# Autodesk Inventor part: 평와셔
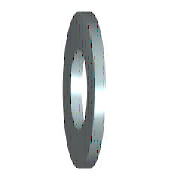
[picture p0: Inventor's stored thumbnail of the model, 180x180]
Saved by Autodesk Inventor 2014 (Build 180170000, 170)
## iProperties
IsCustomPart: 1
Created: 2012-02
Part Number: 평와셔
Material: 강철
Description: 평면 와셔 - 초대형 시리즈 - 제품 등급 C
Document SubType Name: Modeling
Standard: ISO 7094
Designer: mduedu
Standard Revision: Second edition 2000-06-01
Standards Organization: ISO
Language: ko-KR
Size Designation: ST 5 - 100 HV
Categories: <MemberInstance><Categories><Category DisplayName="조임쇠" InternalName="e4da775c-781d-43d5-af7c-5136215cf5a6" Mnemonic="FSTN"><Category DisplayName="와셔" InternalN
Density: 7.85 g/cm^3
Appearance: 강철
Mass: 3.62216 g
Surface Area: 6.09076 cm^2
Volume: 0.461421 cm^3
Author: mduedu
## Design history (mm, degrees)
sketch "스케치"
  geometry: C1 r 9 at (0, 0); C2 r 2.75 at (0, 0); 1 further point
  constraints: 2 centre point, 2 coincident
  dimensions: "d0" = 5.5 diameter of C2 (= SD1); "d1" = 18 diameter of C1 (= SD2)
extrude "본체" new body sketch "스케치" distance "d2" = 2 (= SD); taper "d3" = 0 deg
workaxis "Work Axis1"
workplane "Work Plane1"
body "Solid1"
other parameters: "SD1" = 5.5 [user parameter; used in 1 equation term], "SD2" = 18 [user parameter; used in 1 equation term], "SD" = 2 [user parameter; used in 1 equation term], "d4" = 0, "d5" = 0, "d6" = 0, "d7" = 0, "NND" = 5 [user parameter]
